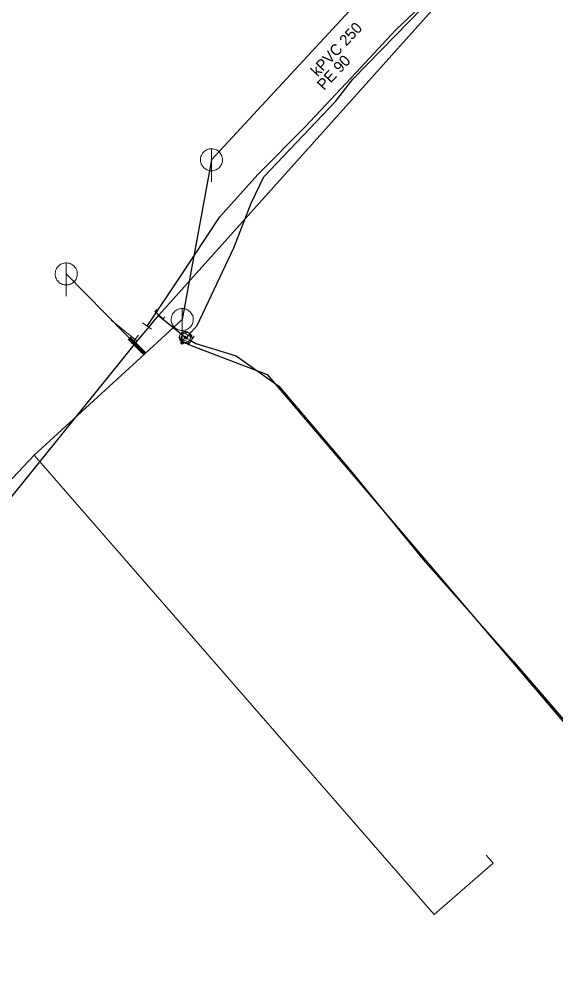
# Model space of a CAD drawing. Extents: x -779496 to -779026, y -977086 to -976624.
# Drawn here: x -779202.2 to -779153.6, y -976850.3 to -976763.6 of the extents above; entities that cross this region are included whole.
import ezdxf

# ---------------------------------------------------------------- set-up
doc = ezdxf.new("R2010")
doc.units = 0
doc.header["$LTSCALE"] = 0.4
doc.linetypes.add('MEDIUM_DASHED', pattern=[4.5, 3, -1.5])
for name, color, linetype, lineweight in [('1', 7, 'MEDIUM_DASHED', 25), ('11', 7, 'Continuous', 13), ('13', 7, 'Continuous', 13), ('14', 7, 'Continuous', 13), ('17', 7, 'Continuous', 25), ('2', 7, 'Continuous', 13), ('22', 7, 'Continuous', 13), ('34', 7, 'Continuous', 13), ('47', 7, 'Continuous', 13), ('9', 7, 'Continuous', 13)]:
    doc.layers.add(name, color=color, linetype=linetype, lineweight=lineweight)

msp = doc.modelspace()

# ---------------------------------------------------------------- linework, layer by layer
at = {"layer": '11'}
msp.add_line((-779197.907, -976786.682), (-779190.807, -976793.919), dxfattribs=at)
msp.add_lwpolyline([(-779159.899, -976839.272), (-779159.281, -976840.015), (-779164.6, -976844.654), (-779200.812, -976803.077)], dxfattribs=at)
at = {"layer": '13'}
msp.add_line((-779191.681, -976792.614), (-779193.835, -976790.879), dxfattribs=at)
at = {"layer": '14', "lineweight": 25}
for p, q in [((-779163.01, -976752.87), (-779184.76, -976776.35)), ((-779184.76, -976776.35), (-779187.41, -976790.809))]:
    msp.add_line(p, q, dxfattribs=at)
at = {"layer": '14'}
for p, q in [((-779191.487, -976792.772), (-779191.681, -976792.614)), ((-779187.299, -976792.639), (-779187.415, -976792.898)), ((-779187.15, -976792.396), (-779187.299, -976792.639)), ((-779187.15, -976792.396), (-779187.008, -976792.482)), ((-779187.008, -976792.482), (-779186.859, -976792.239)), ((-779186.629, -976792.713), (-779187.008, -976792.482))]:
    msp.add_line(p, q, dxfattribs=at)
at = {"layer": '14', "lineweight": 25}
msp.add_lwpolyline([(-779187.41, -976790.809), (-779190.807, -976793.919), (-779200.812, -976803.077), (-779239.083, -976843.704), (-779240.711, -976845.665), (-779251.651, -976858.85), (-779257.611, -976867.208)], dxfattribs=at)
at = {"layer": '17'}
for points in [[(-779189.518, -976790.412), (-779134.866, -976729.399), (-779129.046, -976723.822), (-779107.515, -976704.401), (-779072.015, -976674.642), (-779065.672, -976669.548)], [(-779190.59, -976791.399), (-779187.539, -976786.859), (-779184, -976781.5), (-779180.57, -976777.69), (-779176.27, -976773.379), (-779172.129, -976768.94), (-779168.039, -976764.55), (-779163.71, -976760.43), (-779163.45, -976760.193), (-779159.149, -976756.27), (-779154.78, -976752.09), (-779154.48, -976751.805)], [(-779186.859, -976792.239), (-779186.07, -976791.355), (-779182.73, -976784.316), (-779181.184, -976780.285), (-779180.028, -976777.886), (-779173.543, -976771.074), (-779171.96, -976769.05), (-779164.37, -976761.23), (-779163.412, -976760.224), (-779163.149, -976759.949)], [(-779276.545, -976891.073), (-779272.473, -976886.943), (-779252.653, -976866.844), (-779246.603, -976859.784), (-779242.228, -976854.603), (-779234.164, -976845.175), (-779227.585, -976837.452), (-779212.579, -976818.883), (-779210.76, -976816.627), (-779191.487, -976792.772), (-779191.372, -976792.629), (-779190.682, -976791.787), (-779189.552, -976790.451), (-779187.15, -976792.396)], [(-779187.682, -976792.625), (-779186.592, -976793.16), (-779179.717, -976795.781), (-779149.307, -976831.449), (-779138.088, -976844.662)], [(-779186.629, -976792.713), (-779186.179, -976792.991), (-779182.515, -976794.103), (-779178.658, -976796.833), (-779172.333, -976804.278), (-779165.603, -976812.539), (-779157.438, -976821.754), (-779149.191, -976831.304), (-779149.079, -976831.467), (-779144.1, -976837.296), (-779138.408, -976844.644)]]:
    msp.add_lwpolyline(points, dxfattribs=at)
at = {"layer": '2', "lineweight": 106}
msp.add_line((-779190.807, -976793.919), (-779192.202, -976792.497), dxfattribs=at)
at = {"layer": '2', "lineweight": 100}
msp.add_line((-779190.807, -976793.919), (-779192.202, -976792.497), dxfattribs=at)
at = {"layer": '22'}
for p, q in [((-779184.76, -976778.35), (-779184.759, -976775.35)), ((-779197.907, -976788.682), (-779197.906, -976785.682)), ((-779187.41, -976792.809), (-779187.409, -976789.809))]:
    msp.add_line(p, q, dxfattribs=at)
for points in [[(-779183.76, -976776.35), (-779183.765, -976776.241), (-779183.783, -976776.133), (-779183.813, -976776.027), (-779183.853, -976775.926), (-779183.905, -976775.829), (-779183.967, -976775.739), (-779184.039, -976775.656), (-779184.119, -976775.582), (-779184.207, -976775.516), (-779184.301, -976775.461), (-779184.401, -976775.416), (-779184.506, -976775.383), (-779184.613, -976775.361), (-779184.722, -976775.351), (-779184.832, -976775.353), (-779184.94, -976775.367), (-779185.047, -976775.392), (-779185.15, -976775.429), (-779185.248, -976775.478), (-779185.34, -976775.536), (-779185.426, -976775.605), (-779185.503, -976775.682), (-779185.572, -976775.768), (-779185.631, -976775.86), (-779185.679, -976775.958), (-779185.716, -976776.061), (-779185.742, -976776.168), (-779185.756, -976776.276), (-779185.759, -976776.386), (-779185.749, -976776.495), (-779185.728, -976776.602), (-779185.694, -976776.706), (-779185.65, -976776.806), (-779185.595, -976776.901), (-779185.529, -976776.989), (-779185.455, -976777.069), (-779185.372, -976777.141), (-779185.282, -976777.203), (-779185.186, -976777.255), (-779185.084, -976777.296), (-779184.979, -976777.326), (-779184.871, -976777.344), (-779184.761, -976777.35), (-779184.652, -976777.344), (-779184.544, -976777.326), (-779184.439, -976777.297), (-779184.337, -976777.256), (-779184.24, -976777.204), (-779184.15, -976777.142), (-779184.067, -976777.071), (-779183.992, -976776.991), (-779183.927, -976776.903), (-779183.871, -976776.809), (-779183.827, -976776.709), (-779183.793, -976776.605), (-779183.771, -976776.497), (-779183.761, -976776.388)], [(-779196.907, -976786.682), (-779196.912, -976786.573), (-779196.93, -976786.465), (-779196.96, -976786.359), (-779197, -976786.258), (-779197.052, -976786.161), (-779197.114, -976786.071), (-779197.186, -976785.988), (-779197.266, -976785.914), (-779197.354, -976785.848), (-779197.448, -976785.793), (-779197.548, -976785.748), (-779197.653, -976785.715), (-779197.76, -976785.693), (-779197.869, -976785.683), (-779197.979, -976785.685), (-779198.087, -976785.699), (-779198.194, -976785.724), (-779198.297, -976785.761), (-779198.395, -976785.81), (-779198.487, -976785.868), (-779198.573, -976785.937), (-779198.65, -976786.014), (-779198.719, -976786.1), (-779198.778, -976786.192), (-779198.826, -976786.29), (-779198.863, -976786.393), (-779198.889, -976786.5), (-779198.903, -976786.608), (-779198.906, -976786.718), (-779198.896, -976786.827), (-779198.875, -976786.934), (-779198.841, -976787.038), (-779198.797, -976787.138), (-779198.742, -976787.233), (-779198.676, -976787.321), (-779198.602, -976787.401), (-779198.519, -976787.473), (-779198.429, -976787.535), (-779198.333, -976787.587), (-779198.231, -976787.628), (-779198.126, -976787.658), (-779198.018, -976787.676), (-779197.908, -976787.682), (-779197.799, -976787.676), (-779197.691, -976787.658), (-779197.586, -976787.629), (-779197.484, -976787.588), (-779197.387, -976787.536), (-779197.297, -976787.474), (-779197.214, -976787.403), (-779197.139, -976787.323), (-779197.074, -976787.235), (-779197.018, -976787.141), (-779196.974, -976787.041), (-779196.94, -976786.937), (-779196.918, -976786.829), (-779196.908, -976786.72)], [(-779186.41, -976790.809), (-779186.415, -976790.7), (-779186.433, -976790.592), (-779186.463, -976790.486), (-779186.503, -976790.385), (-779186.555, -976790.288), (-779186.617, -976790.198), (-779186.689, -976790.115), (-779186.769, -976790.041), (-779186.857, -976789.975), (-779186.951, -976789.92), (-779187.051, -976789.875), (-779187.156, -976789.842), (-779187.263, -976789.82), (-779187.372, -976789.81), (-779187.482, -976789.812), (-779187.59, -976789.826), (-779187.697, -976789.851), (-779187.8, -976789.888), (-779187.898, -976789.937), (-779187.99, -976789.995), (-779188.076, -976790.064), (-779188.153, -976790.141), (-779188.222, -976790.227), (-779188.281, -976790.319), (-779188.329, -976790.417), (-779188.366, -976790.52), (-779188.392, -976790.627), (-779188.406, -976790.735), (-779188.409, -976790.845), (-779188.399, -976790.954), (-779188.378, -976791.061), (-779188.344, -976791.165), (-779188.3, -976791.265), (-779188.245, -976791.36), (-779188.179, -976791.448), (-779188.105, -976791.528), (-779188.022, -976791.6), (-779187.932, -976791.662), (-779187.836, -976791.714), (-779187.734, -976791.755), (-779187.629, -976791.785), (-779187.521, -976791.803), (-779187.411, -976791.809), (-779187.302, -976791.803), (-779187.194, -976791.785), (-779187.089, -976791.756), (-779186.987, -976791.715), (-779186.89, -976791.663), (-779186.8, -976791.601), (-779186.717, -976791.53), (-779186.642, -976791.45), (-779186.577, -976791.362), (-779186.521, -976791.268), (-779186.477, -976791.168), (-779186.443, -976791.064), (-779186.421, -976790.956), (-779186.411, -976790.847)]]:
    msp.add_lwpolyline(points, close=True, dxfattribs=at)
at = {"layer": '34'}
for p, q in [((-779191.005, -976791.12), (-779190.175, -976791.678)), ((-779187.285, -976791.978), (-779186.433, -976792.5)), ((-779191.364, -976792.227), (-779191.998, -976793)), ((-779187.744, -976792.411), (-779186.854, -976792.867)), ((-779186.343, -976792.302), (-779186.915, -976793.122))]:
    msp.add_line(p, q, dxfattribs=at)
at = {"layer": '47'}
msp.add_lwpolyline([(-779188.98, -976790.555), (-779189.148, -976790.742), (-779189.887, -976790.081), (-779189.719, -976789.893)], dxfattribs=at)
for points in [[(-779186.757, -976792.705), (-779186.727, -976792.662), (-779186.701, -976792.616), (-779186.681, -976792.568), (-779186.665, -976792.519), (-779186.655, -976792.467), (-779186.65, -976792.414), (-779186.651, -976792.363), (-779186.658, -976792.311), (-779186.669, -976792.26), (-779186.685, -976792.21), (-779186.707, -976792.162), (-779186.735, -976792.118), (-779186.765, -976792.076), (-779186.801, -976792.037), (-779186.84, -976792.003), (-779186.883, -976791.973), (-779186.929, -976791.947), (-779186.977, -976791.926), (-779187.026, -976791.911), (-779187.078, -976791.901), (-779187.131, -976791.896), (-779187.183, -976791.897), (-779187.235, -976791.903), (-779187.286, -976791.914), (-779187.335, -976791.931), (-779187.383, -976791.953), (-779187.428, -976791.98), (-779187.469, -976792.011), (-779187.508, -976792.047), (-779187.542, -976792.086), (-779187.572, -976792.129), (-779187.598, -976792.175), (-779187.619, -976792.223), (-779187.634, -976792.272), (-779187.644, -976792.324), (-779187.65, -976792.376), (-779187.649, -976792.429), (-779187.643, -976792.481), (-779187.631, -976792.532), (-779187.614, -976792.581), (-779187.592, -976792.629), (-779187.566, -976792.674), (-779187.534, -976792.715), (-779187.498, -976792.754), (-779187.459, -976792.788), (-779187.416, -976792.818), (-779187.37, -976792.844), (-779187.323, -976792.865), (-779187.273, -976792.88), (-779187.221, -976792.89), (-779187.169, -976792.896), (-779187.117, -976792.894), (-779187.065, -976792.888), (-779187.014, -976792.876), (-779186.964, -976792.86), (-779186.916, -976792.838), (-779186.872, -976792.811), (-779186.83, -976792.78), (-779186.791, -976792.744)], [(-779186.746, -976792.055), (-779186.792, -976792.031), (-779186.841, -976792.01), (-779186.89, -976791.996), (-779186.942, -976791.986), (-779186.994, -976791.982), (-779187.047, -976791.983), (-779187.098, -976791.991), (-779187.149, -976792.003), (-779187.198, -976792.02), (-779187.246, -976792.042), (-779187.291, -976792.07), (-779187.332, -976792.102), (-779187.37, -976792.137), (-779187.404, -976792.177), (-779187.434, -976792.22), (-779187.458, -976792.266), (-779187.479, -976792.315), (-779187.493, -976792.365), (-779187.503, -976792.416), (-779187.507, -976792.468), (-779187.506, -976792.521), (-779187.499, -976792.573), (-779187.487, -976792.624), (-779187.47, -976792.673), (-779187.447, -976792.72), (-779187.419, -976792.765), (-779187.388, -976792.807), (-779187.352, -976792.844), (-779187.312, -976792.878), (-779187.269, -976792.908), (-779187.223, -976792.932), (-779187.174, -976792.953), (-779187.124, -976792.968), (-779187.073, -976792.977), (-779187.021, -976792.981), (-779186.969, -976792.98), (-779186.916, -976792.974), (-779186.865, -976792.962), (-779186.816, -976792.944), (-779186.769, -976792.921), (-779186.724, -976792.893), (-779186.683, -976792.862), (-779186.645, -976792.826), (-779186.611, -976792.786), (-779186.581, -976792.743), (-779186.557, -976792.697), (-779186.536, -976792.648), (-779186.521, -976792.599), (-779186.512, -976792.547), (-779186.508, -976792.495), (-779186.509, -976792.443), (-779186.516, -976792.391), (-779186.528, -976792.34), (-779186.546, -976792.291), (-779186.568, -976792.243), (-779186.596, -976792.198), (-779186.627, -976792.158), (-779186.663, -976792.119), (-779186.703, -976792.085)], [(-779187.085, -976792.446), (-779187.08, -976792.439), (-779187.076, -976792.432), (-779187.073, -976792.424), (-779187.07, -976792.416), (-779187.068, -976792.407), (-779187.068, -976792.399), (-779187.068, -976792.39), (-779187.069, -976792.382), (-779187.071, -976792.373), (-779187.073, -976792.365), (-779187.077, -976792.357), (-779187.082, -976792.35), (-779187.087, -976792.343), (-779187.092, -976792.337), (-779187.099, -976792.331), (-779187.106, -976792.326), (-779187.113, -976792.322), (-779187.121, -976792.319), (-779187.129, -976792.316), (-779187.138, -976792.314), (-779187.146, -976792.314), (-779187.155, -976792.314), (-779187.163, -976792.315), (-779187.172, -976792.316), (-779187.18, -976792.319), (-779187.188, -976792.323), (-779187.195, -976792.328), (-779187.202, -976792.333), (-779187.208, -976792.338), (-779187.214, -976792.345), (-779187.219, -976792.352), (-779187.223, -976792.359), (-779187.226, -976792.367), (-779187.229, -976792.375), (-779187.231, -976792.384), (-779187.232, -976792.392), (-779187.231, -976792.401), (-779187.23, -976792.409), (-779187.229, -976792.418), (-779187.226, -976792.426), (-779187.222, -976792.434), (-779187.217, -976792.441), (-779187.212, -976792.448), (-779187.207, -976792.454), (-779187.2, -976792.46), (-779187.193, -976792.465), (-779187.186, -976792.469), (-779187.178, -976792.472), (-779187.17, -976792.475), (-779187.161, -976792.477), (-779187.153, -976792.478), (-779187.144, -976792.477), (-779187.136, -976792.476), (-779187.127, -976792.474), (-779187.119, -976792.472), (-779187.111, -976792.468), (-779187.104, -976792.463), (-779187.097, -976792.458), (-779187.091, -976792.453)], [(-779186.965, -976792.412), (-779186.972, -976792.407), (-779186.98, -976792.404), (-779186.988, -976792.402), (-779186.996, -976792.4), (-779187.005, -976792.4), (-779187.014, -976792.4), (-779187.023, -976792.401), (-779187.031, -976792.403), (-779187.039, -976792.406), (-779187.047, -976792.409), (-779187.054, -976792.414), (-779187.061, -976792.419), (-779187.067, -976792.425), (-779187.073, -976792.431), (-779187.077, -976792.439), (-779187.082, -976792.446), (-779187.085, -976792.454), (-779187.087, -976792.462), (-779187.089, -976792.47), (-779187.089, -976792.479), (-779187.089, -976792.488), (-779187.088, -976792.497), (-779187.086, -976792.505), (-779187.083, -976792.514), (-779187.08, -976792.521), (-779187.075, -976792.528), (-779187.07, -976792.535), (-779187.064, -976792.541), (-779187.058, -976792.547), (-779187.05, -976792.551), (-779187.043, -976792.556), (-779187.035, -976792.559), (-779187.027, -976792.561), (-779187.019, -976792.563), (-779187.01, -976792.563), (-779187.002, -976792.564), (-779186.992, -976792.562), (-779186.984, -976792.56), (-779186.975, -976792.557), (-779186.968, -976792.554), (-779186.961, -976792.549), (-779186.954, -976792.544), (-779186.948, -976792.538), (-779186.942, -976792.532), (-779186.938, -976792.524), (-779186.933, -976792.517), (-779186.93, -976792.509), (-779186.928, -976792.501), (-779186.926, -976792.493), (-779186.926, -976792.484), (-779186.925, -976792.476), (-779186.927, -976792.466), (-779186.929, -976792.458), (-779186.932, -976792.45), (-779186.935, -976792.442), (-779186.94, -976792.435), (-779186.945, -976792.428), (-779186.951, -976792.422), (-779186.957, -976792.416)]]:
    msp.add_lwpolyline(points, close=True, dxfattribs=at)
at = {"layer": '9'}
for points in [[(-779187.541, -976792.898), (-779187.541, -976792.911), (-779187.539, -976792.924), (-779187.536, -976792.937), (-779187.531, -976792.949), (-779187.525, -976792.961), (-779187.518, -976792.972), (-779187.51, -976792.982), (-779187.5, -976792.992), (-779187.49, -976793), (-779187.479, -976793.007), (-779187.467, -976793.013), (-779187.455, -976793.018), (-779187.442, -976793.021), (-779187.429, -976793.023), (-779187.416, -976793.025), (-779187.403, -976793.024), (-779187.39, -976793.022), (-779187.377, -976793.019), (-779187.365, -976793.014), (-779187.353, -976793.008), (-779187.342, -976793.001), (-779187.332, -976792.993), (-779187.322, -976792.983), (-779187.314, -976792.973), (-779187.307, -976792.962), (-779187.301, -976792.95), (-779187.296, -976792.938), (-779187.293, -976792.925), (-779187.291, -976792.912), (-779187.289, -976792.899), (-779187.29, -976792.886), (-779187.292, -976792.873), (-779187.295, -976792.86), (-779187.3, -976792.848), (-779187.306, -976792.836), (-779187.313, -976792.825), (-779187.321, -976792.815), (-779187.331, -976792.805), (-779187.341, -976792.797), (-779187.352, -976792.79), (-779187.364, -976792.784), (-779187.376, -976792.779), (-779187.389, -976792.776), (-779187.402, -976792.774), (-779187.415, -976792.773), (-779187.428, -976792.773), (-779187.441, -976792.775), (-779187.454, -976792.778), (-779187.466, -976792.783), (-779187.478, -976792.789), (-779187.489, -976792.796), (-779187.499, -976792.804), (-779187.509, -976792.814), (-779187.517, -976792.824), (-779187.524, -976792.835), (-779187.53, -976792.847), (-779187.535, -976792.859), (-779187.538, -976792.872), (-779187.54, -976792.885)], [(-779187.521, -976792.898), (-779187.522, -976792.909), (-779187.52, -976792.92), (-779187.517, -976792.931), (-779187.513, -976792.941), (-779187.508, -976792.951), (-779187.502, -976792.96), (-779187.495, -976792.969), (-779187.487, -976792.977), (-779187.478, -976792.984), (-779187.469, -976792.99), (-779187.459, -976792.995), (-779187.449, -976792.999), (-779187.438, -976793.002), (-779187.427, -976793.005), (-779187.416, -976793.005), (-779187.405, -976793.005), (-779187.394, -976793.003), (-779187.383, -976793), (-779187.373, -976792.996), (-779187.363, -976792.991), (-779187.354, -976792.985), (-779187.345, -976792.978), (-779187.337, -976792.97), (-779187.33, -976792.961), (-779187.324, -976792.952), (-779187.319, -976792.942), (-779187.315, -976792.932), (-779187.312, -976792.921), (-779187.31, -976792.91), (-779187.309, -976792.899), (-779187.309, -976792.888), (-779187.311, -976792.877), (-779187.314, -976792.866), (-779187.318, -976792.856), (-779187.323, -976792.846), (-779187.329, -976792.837), (-779187.336, -976792.828), (-779187.344, -976792.82), (-779187.353, -976792.813), (-779187.362, -976792.807), (-779187.372, -976792.802), (-779187.382, -976792.798), (-779187.393, -976792.795), (-779187.404, -976792.793), (-779187.415, -976792.793), (-779187.426, -976792.792), (-779187.437, -976792.794), (-779187.448, -976792.797), (-779187.458, -976792.801), (-779187.468, -976792.806), (-779187.477, -976792.812), (-779187.486, -976792.819), (-779187.494, -976792.827), (-779187.501, -976792.836), (-779187.507, -976792.845), (-779187.512, -976792.855), (-779187.516, -976792.865), (-779187.519, -976792.876), (-779187.521, -976792.887)], [(-779187.502, -976792.898), (-779187.502, -976792.907), (-779187.501, -976792.916), (-779187.498, -976792.925), (-779187.495, -976792.933), (-779187.491, -976792.941), (-779187.486, -976792.949), (-779187.48, -976792.956), (-779187.474, -976792.962), (-779187.467, -976792.968), (-779187.459, -976792.973), (-779187.451, -976792.977), (-779187.443, -976792.98), (-779187.434, -976792.983), (-779187.425, -976792.984), (-779187.416, -976792.986), (-779187.407, -976792.985), (-779187.398, -976792.984), (-779187.389, -976792.981), (-779187.381, -976792.978), (-779187.373, -976792.974), (-779187.365, -976792.969), (-779187.358, -976792.963), (-779187.352, -976792.957), (-779187.346, -976792.95), (-779187.341, -976792.942), (-779187.337, -976792.934), (-779187.334, -976792.926), (-779187.331, -976792.917), (-779187.33, -976792.908), (-779187.328, -976792.899), (-779187.329, -976792.89), (-779187.33, -976792.881), (-779187.333, -976792.872), (-779187.336, -976792.864), (-779187.34, -976792.856), (-779187.345, -976792.848), (-779187.351, -976792.841), (-779187.357, -976792.835), (-779187.364, -976792.829), (-779187.372, -976792.824), (-779187.38, -976792.82), (-779187.388, -976792.817), (-779187.397, -976792.814), (-779187.406, -976792.813), (-779187.415, -976792.812), (-779187.424, -976792.812), (-779187.433, -976792.813), (-779187.442, -976792.816), (-779187.45, -976792.819), (-779187.458, -976792.823), (-779187.466, -976792.828), (-779187.473, -976792.834), (-779187.479, -976792.84), (-779187.485, -976792.847), (-779187.49, -976792.855), (-779187.494, -976792.863), (-779187.497, -976792.871), (-779187.5, -976792.88), (-779187.501, -976792.889)], [(-779187.482, -976792.898), (-779187.482, -976792.905), (-779187.481, -976792.912), (-779187.48, -976792.919), (-779187.477, -976792.925), (-779187.474, -976792.931), (-779187.47, -976792.937), (-779187.466, -976792.943), (-779187.461, -976792.948), (-779187.455, -976792.952), (-779187.449, -976792.956), (-779187.443, -976792.959), (-779187.437, -976792.962), (-779187.43, -976792.963), (-779187.423, -976792.966), (-779187.416, -976792.966), (-779187.409, -976792.966), (-779187.402, -976792.964), (-779187.395, -976792.963), (-779187.389, -976792.96), (-779187.382, -976792.957), (-779187.377, -976792.953), (-779187.371, -976792.949), (-779187.366, -976792.944), (-779187.362, -976792.938), (-779187.358, -976792.932), (-779187.355, -976792.926), (-779187.352, -976792.92), (-779187.35, -976792.913), (-779187.349, -976792.906), (-779187.348, -976792.899), (-779187.348, -976792.892), (-779187.349, -976792.885), (-779187.351, -976792.878), (-779187.354, -976792.872), (-779187.357, -976792.865), (-779187.361, -976792.86), (-779187.365, -976792.854), (-779187.37, -976792.849), (-779187.376, -976792.845), (-779187.381, -976792.841), (-779187.388, -976792.838), (-779187.394, -976792.835), (-779187.401, -976792.833), (-779187.408, -976792.832), (-779187.415, -976792.832), (-779187.422, -976792.832), (-779187.429, -976792.832), (-779187.436, -976792.834), (-779187.442, -976792.837), (-779187.448, -976792.84), (-779187.454, -976792.844), (-779187.46, -976792.848), (-779187.465, -976792.853), (-779187.469, -976792.859), (-779187.473, -976792.864), (-779187.476, -976792.871), (-779187.479, -976792.877), (-779187.48, -976792.884), (-779187.482, -976792.891)], [(-779187.462, -976792.898), (-779187.462, -976792.903), (-779187.462, -976792.908), (-779187.461, -976792.913), (-779187.459, -976792.917), (-779187.457, -976792.922), (-779187.454, -976792.926), (-779187.451, -976792.929), (-779187.447, -976792.933), (-779187.444, -976792.936), (-779187.44, -976792.939), (-779187.435, -976792.941), (-779187.431, -976792.943), (-779187.426, -976792.944), (-779187.421, -976792.946), (-779187.416, -976792.946), (-779187.411, -976792.946), (-779187.406, -976792.945), (-779187.401, -976792.944), (-779187.397, -976792.942), (-779187.392, -976792.94), (-779187.388, -976792.937), (-779187.384, -976792.934), (-779187.381, -976792.93), (-779187.378, -976792.927), (-779187.375, -976792.923), (-779187.373, -976792.918), (-779187.371, -976792.914), (-779187.37, -976792.909), (-779187.369, -976792.904), (-779187.368, -976792.899), (-779187.368, -976792.894), (-779187.369, -976792.889), (-779187.37, -976792.884), (-779187.372, -976792.88), (-779187.374, -976792.875), (-779187.377, -976792.871), (-779187.38, -976792.867), (-779187.383, -976792.864), (-779187.387, -976792.861), (-779187.391, -976792.858), (-779187.396, -976792.856), (-779187.4, -976792.854), (-779187.405, -976792.853), (-779187.41, -976792.852), (-779187.415, -976792.852), (-779187.42, -976792.852), (-779187.425, -976792.853), (-779187.43, -976792.853), (-779187.434, -976792.855), (-779187.439, -976792.857), (-779187.443, -976792.86), (-779187.446, -976792.863), (-779187.45, -976792.866), (-779187.453, -976792.87), (-779187.456, -976792.874), (-779187.458, -976792.879), (-779187.46, -976792.883), (-779187.461, -976792.888), (-779187.462, -976792.893)], [(-779187.442, -976792.898), (-779187.442, -976792.901), (-779187.443, -976792.904), (-779187.442, -976792.906), (-779187.441, -976792.909), (-779187.44, -976792.912), (-779187.438, -976792.914), (-779187.436, -976792.916), (-779187.434, -976792.918), (-779187.432, -976792.92), (-779187.43, -976792.922), (-779187.427, -976792.924), (-779187.424, -976792.925), (-779187.422, -976792.925), (-779187.419, -976792.926), (-779187.416, -976792.926), (-779187.413, -976792.926), (-779187.41, -976792.926), (-779187.407, -976792.925), (-779187.405, -976792.924), (-779187.402, -976792.923), (-779187.4, -976792.921), (-779187.397, -976792.919), (-779187.395, -976792.917), (-779187.394, -976792.915), (-779187.392, -976792.913), (-779187.391, -976792.91), (-779187.389, -976792.907), (-779187.389, -976792.905), (-779187.388, -976792.902), (-779187.387, -976792.899), (-779187.388, -976792.896), (-779187.388, -976792.893), (-779187.389, -976792.89), (-779187.39, -976792.888), (-779187.391, -976792.885), (-779187.393, -976792.883), (-779187.394, -976792.88), (-779187.396, -976792.878), (-779187.399, -976792.877), (-779187.401, -976792.875), (-779187.404, -976792.874), (-779187.406, -976792.873), (-779187.409, -976792.872), (-779187.412, -976792.872), (-779187.415, -976792.871), (-779187.418, -976792.872), (-779187.421, -976792.871), (-779187.423, -976792.873), (-779187.426, -976792.873), (-779187.429, -976792.874), (-779187.431, -976792.876), (-779187.433, -976792.877), (-779187.435, -976792.879), (-779187.437, -976792.882), (-779187.439, -976792.884), (-779187.44, -976792.887), (-779187.441, -976792.889), (-779187.442, -976792.892), (-779187.442, -976792.895)], [(-779187.423, -976792.898), (-779187.423, -976792.9), (-779187.423, -976792.9), (-779187.422, -976792.9), (-779187.422, -976792.902), (-779187.423, -976792.903), (-779187.421, -976792.903), (-779187.421, -976792.903), (-779187.421, -976792.905), (-779187.421, -976792.905), (-779187.42, -976792.906), (-779187.418, -976792.906), (-779187.418, -976792.906), (-779187.418, -976792.907), (-779187.416, -976792.907), (-779187.416, -976792.907), (-779187.415, -976792.907), (-779187.414, -976792.907), (-779187.414, -976792.906), (-779187.413, -976792.906), (-779187.411, -976792.906), (-779187.411, -976792.905), (-779187.411, -976792.905), (-779187.41, -976792.904), (-779187.41, -976792.904), (-779187.408, -976792.903), (-779187.408, -976792.902), (-779187.407, -976792.901), (-779187.407, -976792.901), (-779187.407, -976792.9), (-779187.407, -976792.899), (-779187.407, -976792.898), (-779187.407, -976792.897), (-779187.407, -976792.897), (-779187.408, -976792.896), (-779187.408, -976792.895), (-779187.409, -976792.894), (-779187.409, -976792.894), (-779187.41, -976792.893), (-779187.41, -976792.893), (-779187.411, -976792.892), (-779187.412, -976792.892), (-779187.413, -976792.891), (-779187.413, -976792.891), (-779187.414, -976792.891), (-779187.415, -976792.891), (-779187.416, -976792.891), (-779187.417, -976792.891), (-779187.417, -976792.891), (-779187.418, -976792.892), (-779187.419, -976792.891), (-779187.42, -976792.893), (-779187.42, -976792.893), (-779187.421, -976792.893), (-779187.421, -976792.893), (-779187.422, -976792.895), (-779187.422, -976792.896), (-779187.422, -976792.897), (-779187.423, -976792.897), (-779187.423, -976792.898)]]:
    msp.add_lwpolyline(points, close=True, dxfattribs=at)

# ---------------------------------------------------------------- texts
at = {"layer": '1'}
for s, p in [('kPVC 250', (-779175.146, -976768.893)), ('PE 90 ', (-779174.579, -976770.121))]:
    msp.add_text(s, height=1, rotation=47, dxfattribs=at).set_placement(p)

doc.saveas('drawing.dxf')
